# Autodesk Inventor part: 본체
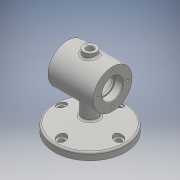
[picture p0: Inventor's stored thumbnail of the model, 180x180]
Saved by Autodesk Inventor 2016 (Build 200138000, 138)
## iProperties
Created: 2018-12
Part Number: 본체
Material: 일반
Document SubType Name: Modeling
Designer: USER
Density: 1 g/cm^3
Appearance: 기본값
Author: USER
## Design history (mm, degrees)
sketch "스케치1"
  geometry: C1 r 55 at (0, 0); 1 further point
  constraints: 1 centre point, 1 coincident
  dimensions: "d0" = 110 diameter of C1
extrude "돌출1" new body sketch "스케치1" distance "d1" = 11; taper "d2" = 0 deg
sketch "스케치2"
  geometry: L1 (35, 75)-(-35, 75); L2 (35, 75)-(35, 105); L3 (35, 105)-(-35, 105); L4 (-35, 105)-(-35, 75); L5 (-55, 0)-(55, 0) reference; L6 (55, 11)-(-55, 11) reference; 2 further points
  constraints: 8 end point, 1 horizontal, 1 midpoint, 1 perpendicular, 1 vertical, 1 vertical alignment
  dimensions: "d3" = 70 distance of L1.start L1.end; "d4" = 30 distance of L1.start L2.end; "d5" = 70 distance of L2.end L3.end; "d6" = 75 distance from line of point (0, 0) L1; "d77" = 11 distance between parallel lines of L5 L6 (derived)
revolve "회전1" sketch "스케치2" stored, may be unused: angle "d7" = 90 deg
node "작업 평면1"
sketch "스케치3"
  geometry: C1 r 10 at (0, 0); 1 further point
  constraints: 1 centre point, 1 coincident
  dimensions: "d9" = 20 diameter of C1
extrude "돌출2" join sketch "스케치3" distance "d10" = 37; taper "d11" = 0 deg
sketch "스케치4"
  geometry: L1 (64, 55)-(64, -55) reference; L2 (75, -55)-(75, 55) reference; C1 r 30 at (0, 0) reference; C2 r 16 at (0, 0); 1 further point
  constraints: 1 centre point, 1 coincident
  dimensions: "d12" = 32 diameter of C2; "d78" = 11 distance between parallel lines of L1 L2 (derived)
extrude "돌출3" cut sketch "스케치4" distance "d13" = 12; taper "d14" = 0 deg
sketch "스케치5"
  geometry: C1 r 16 at (0, 0) reference; C2 r 14 at (0, 0); 1 further point
  constraints: 1 centre point, 1 coincident
  dimensions: "d15" = 28 diameter of C2
extrude "돌출4" cut sketch "스케치5" distance "d16" = 3; taper "d17" = 0 deg
sketch "스케치6"
  geometry: C1 r 14 at (0, 0) reference; C2 r 25 at (0, 0); 1 further point
  constraints: 1 centre point, 1 coincident
  dimensions: "d18" = 50 diameter of C2
extrude "돌출5" cut sketch "스케치6" distance "d19" = 40; taper "d20" = 0 deg
sketch "스케치7"
  geometry: C1 r 30 at (0, 0) reference; C2 r 16 at (0, 0); 1 further point
  constraints: 1 centre point, 1 coincident
  dimensions: "d21" = 32 diameter of C2
extrude "돌출6" cut sketch "스케치7" distance "d22" = 12; taper "d23" = 0 deg
sketch "스케치8"
  geometry: C1 r 16 at (0, 0) reference; C2 r 14 at (0, 0); 1 further point
  constraints: 1 centre point, 1 coincident
  dimensions: "d24" = 28 diameter of C2
extrude "돌출7" cut sketch "스케치8" distance "d25" = 3; taper "d26" = 0 deg
sketch "스케치9"
  geometry: C1 r 5 at (0, 0); 1 further point
  constraints: 1 centre point, 1 coincident
  dimensions: "d27" = 10 diameter of C1
extrude "돌출8" cut sketch "스케치9" stored distance "d28" = 3; taper "d29" = 0 deg; dims "d12" = 32
sketch "스케치10"
  geometry: C1 r 12 at (0, 0); 1 further point
  constraints: 1 centre point, 1 coincident
  dimensions: "d30" = 24 diameter of C1
extrude "돌출9" join sketch "스케치10" stored distance "d31" = 3; taper "d32" = 0 deg
sketch "스케치11"
  geometry: L1 (55, 11)-(-55, 11) reference; L2 (-55, 0)-(55, 0) reference; L3 (55, 11)-(-55, 11) reference; L4 (-55, 11)-(0, 25.737); L5 (-55, 11)-(1.94, 11); L6 (0, 25.737)-(0, 0); L7 (-55, 0)-(55, 0) reference; L8 (-55, 0)-(-55, 11); L9 (-55, 0)-(-55, 11) reference; L10 (-55, 0)-(0, 0); 1 further point
  constraints: 10 end point, 2 collinear, 2 midpoint, 1 equal length, 1 horizontal, 1 vertical alignment
  dimensions: "d34" = 15 deg angle of L5 L4
revolve "회전2" sketch "스케치11" stored, may be unused: angle "d35" = 90 deg
sketch "스케치12"
  geometry: C1 r 16 at (0, 0) reference; C2 r 30 at (0, 0) reference; 2 further points
  constraints: 1 horizontal alignment
  dimensions: "d36" = 23 distance of C1.centre point (23, 0)
hole "구멍1" sketch "스케치12" at (23, 0) diameter "d37" = 3.242; stored, may be unused: countersink angle "d41" = 90 deg, drill point angle "d43" = 118 deg; dims "d38" = 8, "d39" = 4, "d40" = 2, "d42" = 10
sketch "스케치13"
  geometry: C1 r 16 at (0, 0) reference; C2 r 30 at (0, 0) reference; 2 further points
  constraints: 1 horizontal alignment
  dimensions: "d47" = 23 distance of C1.centre point (-23, 0)
hole "구멍2" sketch "스케치13" at (-23, 0) diameter "d48" = 3.242; stored, may be unused: countersink angle "d52" = 90 deg, drill point angle "d54" = 118 deg; dims "d49" = 8, "d50" = 4, "d51" = 2, "d53" = 10
sketch "스케치14"
  geometry: C1 r 4.5 at (-44, 0); 1 further point
  constraints: 1 centre point, 1 horizontal alignment
  dimensions: "d58" = 9 diameter of C1; "d59" = 44 distance of point (0, 0) C1.centre
extrude "돌출10" cut sketch "스케치14" distance "d60" = 10; taper "d61" = 0 deg
sketch "스케치15"
  geometry: C1 r 4.5 at (0, 0) reference; C2 r 7 at (0, 0); 1 further point
  constraints: 1 centre point, 1 coincident
  dimensions: "d62" = 14 diameter of C2
extrude "돌출11" cut sketch "스케치15" distance "d63" = 10; taper "d64" = 0 deg
node "작업 평면2"
sketch "스케치16"
  geometry: L1 (-35, -30)-(-35, 30) reference; L2 (-35, 30)-(35, 30) reference; 2 further points
  constraints: 1 other
  dimensions: "d68" = 35 distance from line of point (0, 0) L1; "d69" = 30 distance from line of point (0, 0) L2
feature "엠보싱1" sketch "스케치16" dims "d70" = 0.5, "d71" = 0
chamfer "모따기1" distance "d72" = 1; stored, may be unused: second distance "d73" = 2, angle "d74" = 45 deg
fillet "모깎기1" dims "d75" = 3
fillet "모깎기2" dims "d76" = 0.3
node "솔리드1"
pattern_circular "원형 패턴1" dims angle "d45" = 360 deg
pattern_circular "원형 패턴2" dims angle "d56" = 360 deg
pattern_circular "원형 패턴3" dims angle "d66" = 360 deg
node "투영된 루프1"
node "투영된 루프2"
node "투영된 루프3"
node "투영된 루프4"
node "투영된 루프5"
node "투영된 루프6"
node "투영된 루프7"
node "투영된 루프8"
node "투영된 루프9"
other parameters: "d8" = 75
